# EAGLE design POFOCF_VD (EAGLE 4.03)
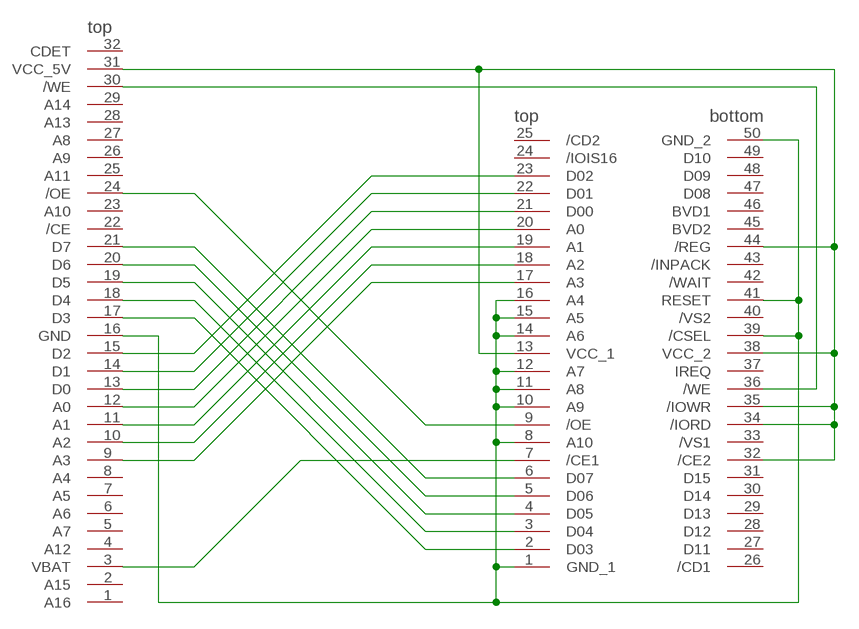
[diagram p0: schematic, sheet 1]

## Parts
U$1  MEMCARD1  [MEMCARD]
U$2  CF_SLOT11  [CF_SLOT1]

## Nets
N$1: U$1.17(D3) U$2.2(D03)
N$2: U$1.18(D4) U$2.3(D04)
N$3: U$1.19(D5) U$2.4(D05)
N$4: U$1.20(D6) U$2.5(D06)
N$5: U$1.21(D7) U$2.6(D07)
N$6: U$1.24(/OE) U$2.9(/OE)
N$7: U$1.11(A1) U$2.19(A1)
N$8: U$1.10(A2) U$2.18(A2)
N$9: U$1.9(A3) U$2.17(A3)
N$10: U$1.12(A0) U$2.20(A0)
N$11: U$1.13(D0) U$2.21(D00)
N$12: U$1.14(D1) U$2.22(D01)
N$13: U$1.15(D2) U$2.23(D02)
N$14: U$1.16(GND) U$2.1(GND_1) U$2.8(A10) U$2.10(A9) U$2.11(A8) U$2.12(A7) U$2.14(A6) U$2.15(A5) U$2.16(A4) U$2.39(/CSEL) U$2.41(RESET) U$2.50(GND_2)
N$15: U$1.3(VBAT) U$2.7(/CE1)
N$16: U$1.30(/WE) U$2.36(/WE)
N$17: U$1.31(VCC_5V) U$2.13(VCC_1) U$2.32(/CE2) U$2.34(/IORD) U$2.35(/IOWR) U$2.38(VCC_2) U$2.44(/REG)
Unconnected: U$1.1(A16) U$1.2(A15) U$1.4(A12) U$1.5(A7) U$1.6(A6) U$1.7(A5) U$1.8(A4) U$1.22(/CE) U$1.23(A10) U$1.25(A11) U$1.26(A9) U$1.27(A8) U$1.28(A13) U$1.29(A14) U$1.32(CDET) U$2.24(/IOIS16) U$2.25(/CD2) U$2.26(/CD1) U$2.27(D11) U$2.28(D12) U$2.29(D13) U$2.30(D14) U$2.31(D15) U$2.33(/VS1) U$2.37(IREQ) U$2.40(/VS2) U$2.42(/WAIT) U$2.43(/INPACK) U$2.45(BVD2) U$2.46(BVD1) U$2.47(D08) U$2.48(D09) U$2.49(D10)

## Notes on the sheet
- top
- top | bottom

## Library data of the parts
U$1 = Atari_Portfolio:MEMCARD: RAM karta Pofo
U$2 = Atari_Portfolio:CF_SLOT1: Patice pro CF kartu

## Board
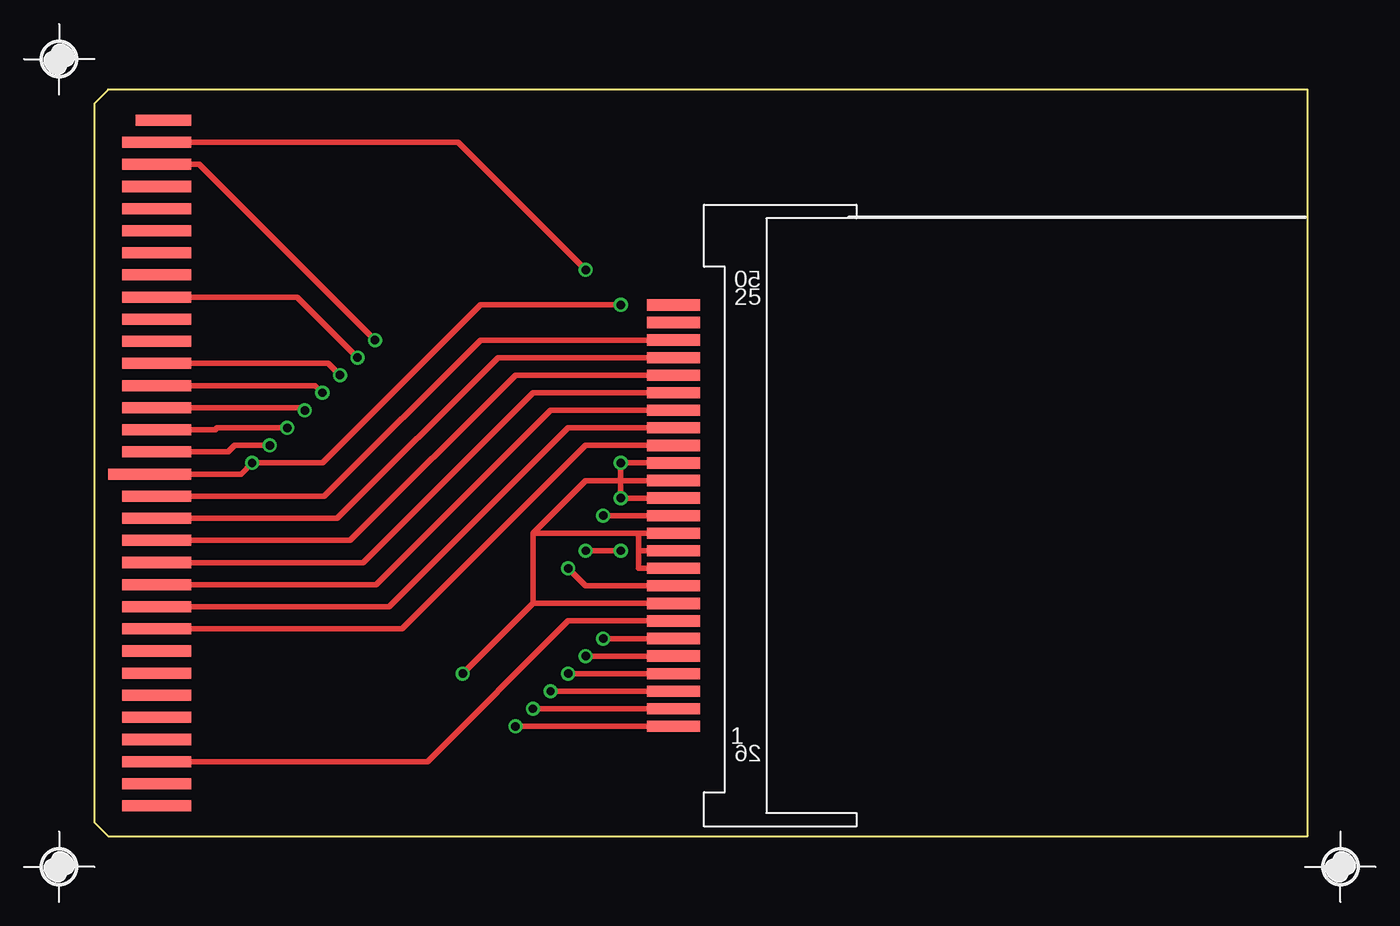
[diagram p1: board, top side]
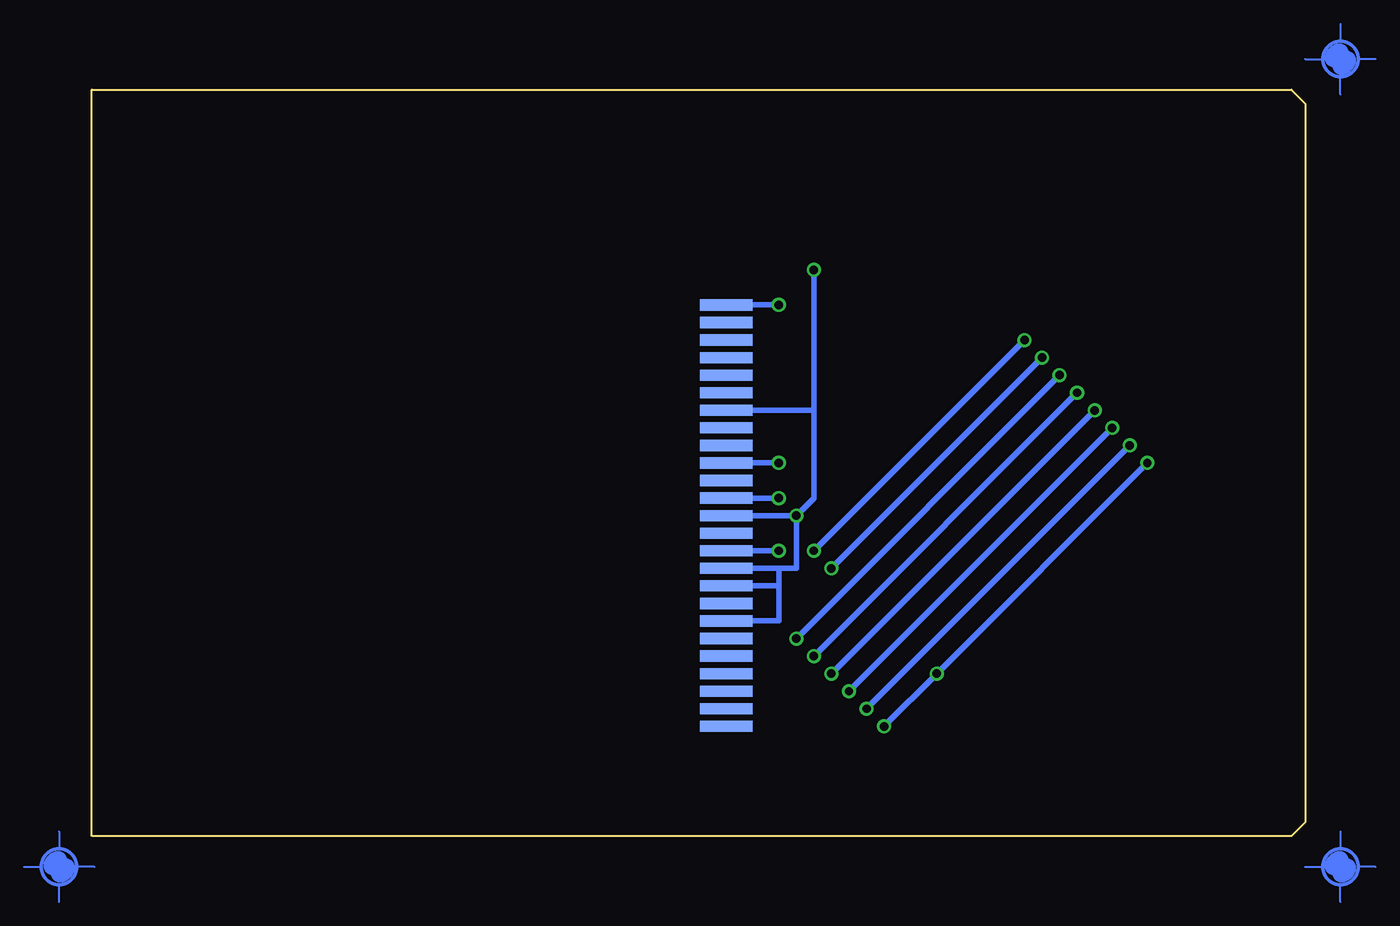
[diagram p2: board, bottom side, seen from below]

Size 87.8 x 54 mm. Coordinates in mm from the lower left corner, seen from the top.
Copper layers used: Top, Bottom

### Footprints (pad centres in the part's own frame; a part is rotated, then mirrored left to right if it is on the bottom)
MEMCARD = smd 5 x 0.8: 1 0.7,-24.8; 2 0.7,-23.2; 3 0.7,-21.6; 4 0.7,-20; 5 0.7,-18.4; 6 0.7,-16.8; 7 0.7,-15.2; 8 0.7,-13.6; 9 0.7,-12; 10 0.7,-10.4; 11 0.7,-8.8; 12 0.7,-7.2; 13 0.7,-5.6; 14 0.7,-4; 15 0.7,-2.4; 17 0.7,0.8; 18 0.7,2.4; 19 0.7,4; 20 0.7,5.6; 21 0.7,7.2; 22 0.7,8.8; 23 0.7,10.4; 24 0.7,12; 25 0.7,13.6; 26 0.7,15.2; 27 0.7,16.8; 28 0.7,18.4; 29 0.7,20; 30 0.7,21.6; 31 0.7,23.2 | smd 6 x 0.8: 16 0.2,-0.8 | smd 4 x 0.8: 32 1.2,24.8
CF_SLOT1 = smd 3.81 x 0.813: 1 3.81,15.24; 2 3.81,13.97; 3 3.81,12.7; 4 3.81,11.43; 5 3.81,10.16; 6 3.81,8.89; 7 3.81,7.62; 8 3.81,6.35; 9 3.81,5.08; 10 3.81,3.81; 11 3.81,2.54; 12 3.81,1.27; 13 3.81,0; 14 3.81,-1.27; 15 3.81,-2.54; 16 3.81,-3.81; 17 3.81,-5.08; 18 3.81,-6.35; 19 3.81,-7.62; 20 3.81,-8.89; 21 3.81,-10.16; 22 3.81,-11.43; 23 3.81,-12.7; 24 3.81,-13.97; 25 3.81,-15.24 | smd 3.81 x 0.813 bottom: 26 3.81,15.24; 27 3.81,13.97; 28 3.81,12.7; 29 3.81,11.43; 30 3.81,10.16; 31 3.81,8.89; 32 3.81,7.62; 33 3.81,6.35; 34 3.81,5.08; 35 3.81,3.81; 36 3.81,2.54; 37 3.81,1.27; 38 3.81,0; 39 3.81,-1.27; 40 3.81,-2.54; 41 3.81,-3.81; 42 3.81,-5.08; 43 3.81,-6.35; 44 3.81,-7.62; 45 3.81,-8.89; 46 3.81,-10.16; 47 3.81,-11.43; 48 3.81,-12.7; 49 3.81,-13.97; 50 3.81,-15.24

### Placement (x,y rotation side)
E$1  [PASS-ROUND]  -2.55,-2.21 0 top
E$2  [PASS-ROUND]  90.16,-2.21 0 top
E$3  [PASS-ROUND]  -2.55,56.21 0 top
U$1  3.8,27 0 top
U$2  45.71,23.19 180 top

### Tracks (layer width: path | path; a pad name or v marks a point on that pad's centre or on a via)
N$1  (via drill 0.61)
  Top 0.406: U$1.17 9.68,27.8 10.15,28.27 v12.69,28.27 | U$2.2 v31.74,9.22
  Bottom 0.406: v12.69,28.27 v31.74,9.22
N$2  (via drill 0.61)
  Top 0.406: v33.01,10.49 U$2.3 | U$1.18 8.74,29.4 8.88,29.54 v13.96,29.54
  Bottom 0.406: v13.96,29.54 v33.01,10.49
N$3  (via drill 0.61)
  Top 0.406: v34.28,11.76 U$2.4 | U$1.19 15.04,31 v15.23,30.81
  Bottom 0.406: v15.23,30.81 v34.28,11.76
N$4  (via drill 0.61)
  Top 0.406: v35.55,13.03 U$2.5 | U$1.20 15.98,32.6 v16.5,32.08
  Bottom 0.406: v16.5,32.08 v35.55,13.03
N$5  (via drill 0.61)
  Top 0.406: v36.82,14.3 U$2.6 | U$1.21 16.92,34.2 v17.77,33.35
  Bottom 0.406: v17.77,33.35 v36.82,14.3
N$6  (via drill 0.61)
  Top 0.406: U$2.9 35.55,18.11 v34.28,19.38 | U$1.24 14.66,39 v19.04,34.62
  Bottom 0.406: v19.04,34.62 v34.28,19.38
N$7
  Top 0.406: U$2.19 33.01,30.81 20.4,18.2 U$1.11
N$8
  Top 0.406: U$2.18 34.28,29.54 21.34,16.6 U$1.10
N$9
  Top 0.406: U$2.17 35.55,28.27 22.28,15 U$1.9
N$10
  Top 0.406: U$2.20 31.74,32.08 19.46,19.8 U$1.12
N$11
  Top 0.406: U$2.21 30.47,33.35 18.52,21.4 U$1.13
N$12
  Top 0.406: U$2.22 29.2,34.62 17.58,23 U$1.14
N$13
  Top 0.406: U$2.23 27.93,35.89 16.64,24.6 U$1.15
N$14  (via drill 0.61)
  Top 0.406: U$2.10 39.36,19.38 39.36,20.65 | 31.74,16.84 31.74,21.92 | v30.47,7.95 U$2.1 | 39.36,20.65 U$2.11 | 39.36,21.92 39.36,20.65 | 31.74,21.92 39.36,21.92 | 39.36,21.92 U$2.12 | 38.09,25.73 35.55,25.73 31.74,21.92 | 38.09,25.73 v38.09,24.46 U$2.39 | 31.74,16.84 U$2.8 | v26.66,11.76 31.74,16.84 | 38.09,25.73 U$2.15 | U$2.41 v38.09,27 38.09,25.73 | v38.09,38.43 27.93,38.43 16.5,27 v11.42,27 10.62,26.2 U$1.16
  Bottom 0.406: v30.47,7.95 v26.66,11.76 v11.42,27 | v38.09,24.46 U$2.39 | v38.09,27 U$2.41 | v38.09,38.43 U$2.50
N$15
  Top 0.406: U$2.7 34.28,15.57 24.11,5.4 U$1.3
N$16  (via drill 0.61)
  Top 0.406: v35.55,20.65 v38.09,20.65 | U$1.30 7.6,48.6 v20.31,35.89
  Bottom 0.406: v38.09,20.65 U$2.36 | v20.31,35.89 v35.55,20.65
N$17  (via drill 0.61)
  Top 0.406: v36.82,23.19 U$2.38 | U$1.31 26.32,50.2 v35.55,40.97
  Bottom 0.406: v35.55,40.97 35.55,30.81 | v36.82,23.19 36.82,19.38 38.09,19.38 | 38.09,19.38 U$2.35 | 38.09,19.38 38.09,18.11 | 38.09,18.11 U$2.34 | U$2.32 38.09,15.57 38.09,18.11 | 35.55,30.81 U$2.44 | 35.55,30.81 35.55,24.46 v36.82,23.19 | v36.82,23.19 U$2.38 v36.82,23.19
